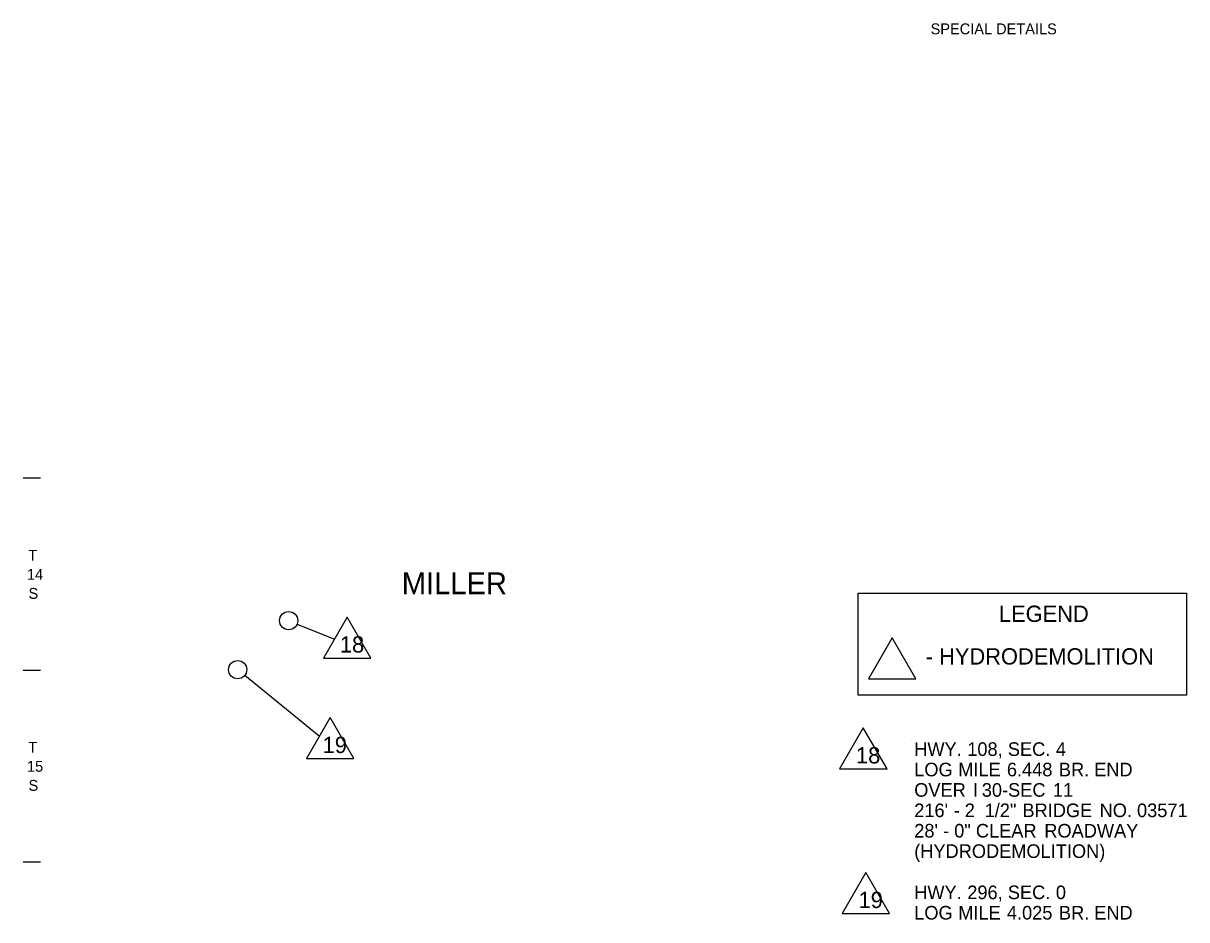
# Model space of a CAD drawing. Extents: x -17668 to 16999, y -17303 to 5867.
# Drawn here: x 10585 to 16998, y -12386 to -7443 of the extents above; entities that cross this region are included whole.
import ezdxf

# ---------------------------------------------------------------- set-up
doc = ezdxf.new("R2010")
doc.units = 0
for name, color, linetype in [('2', 7, 'Continuous'), ('42', 7, 'Continuous'), ('48', 7, 'Continuous'), ('Default', 7, 'Continuous')]:
    doc.layers.add(name, color=color, linetype=linetype)

msp = doc.modelspace()

# ---------------------------------------------------------------- linework, layer by layer
at = {"layer": '48'}
for p, q in [((12094.1, -10756), (12300.3, -10839.1)), ((12370.9, -10716.9), (12240.3, -10943.1)), ((12501.5, -10943.1), (12370.9, -10716.9)), ((15374.6, -10830.8), (15244, -11057)), ((15505.2, -11057), (15374.6, -10830.8)), ((12240.3, -10943.1), (12501.5, -10943.1)), ((12216.9, -11373.6), (11805.8, -11038.5)), ((15244, -11057), (15505.2, -11057)), ((12276.1, -11271.1), (12145.5, -11497.3)), ((12406.7, -11497.3), (12276.1, -11271.1)), ((15215.3, -11328.3), (15084.7, -11554.5)), ((15345.9, -11554.5), (15215.3, -11328.3)), ((15481.4, -11392.6), (15481.4, -11392.6)), ((12145.5, -11497.3), (12406.7, -11497.3)), ((15084.7, -11554.5), (15345.9, -11554.5)), ((15229.9, -12125.8), (15099.3, -12352)), ((15360.5, -12352), (15229.9, -12125.8)), ((15099.3, -12352), (15360.5, -12352))]:
    msp.add_line(p, q, dxfattribs=at)
msp.add_lwpolyline([(15186.8, -10584.9), (16997.4, -10584.9), (16997.4, -11147.5), (15186.8, -11147.5)], close=True, dxfattribs=at)
for centre in [(12048, -10736.7), (11767, -11006.9)]:
    msp.add_circle(centre, 50, dxfattribs=at)
at = {"layer": 'Default'}
for p, q in [((10680.3, -9951.1), (10585.3, -9951.1)), ((10680.3, -11011.5), (10585.3, -11011.5)), ((10680.3, -12068.3), (10585.3, -12068.3))]:
    msp.add_line(p, q, dxfattribs=at)

# ---------------------------------------------------------------- texts
at = {"layer": '2'}
for s, p in [('T', (10613.2, -10406.3)), ('14', (10605.9, -10511.3)), ('S', (10614.4, -10616.3)), ('T', (10613.2, -11464.9)), ('15', (10605.9, -11569.9)), ('S', (10614.4, -11674.9))]:
    msp.add_text(s, height=60, rotation=360, dxfattribs=at).set_placement(p)
msp.add_text('MILLER', height=120, dxfattribs=at).set_placement((12671.5, -10590.7))
at = {"layer": '42'}
msp.add_text('SPECIAL DETAILS', height=60, dxfattribs=at).set_placement((15586.1, -7503.5))
at = {"layer": '48'}
for s, p in [('LEGEND', (15963, -10743.8)), ('18', (12330.5, -10912.7)), ('- HYDRODEMOLITION', (15559.6, -10978.7)), ('19', (12235.3, -11466.9)), ('18', (15174.9, -11524.1)), ('19', (15189.2, -12321.6))]:
    msp.add_text(s, height=90, dxfattribs=at).set_placement(p)
at = {"layer": 'Default'}
for s, p in [('HWY.', (15496, -11482.6)), (' 108,', (15760.5, -11482.6)), (' SEC.', (15984.1, -11482.6)), (' 4', (16248.7, -11482.6)), ('LOG', (15496, -11595.1)), (' MILE', (15710.7, -11595.1)), (' 6.448', (15978.8, -11595.1)), (' BR.', (16265.4, -11595.1)), (' END', (16460, -11595.1)), ('OVER', (15496, -11707.6)), (' I', (15791.6, -11707.6)), (' 30-SEC', (15840.5, -11707.6)), (' 11', (16232.3, -11707.6)), ("216'", (15496, -11820.1)), (' -', (15685.9, -11820.1)), (' 2', (15746.6, -11820.1)), ('  1/2"', (15828.4, -11820.1)), (' BRIDGE', (16064.5, -11820.1)), (' NO.', (16489.8, -11820.1)), (' 03571', (16696, -11820.1)), ("28'", (15496, -11932.6)), (' 0"', (15688.3, -11932.6)), (' CLEAR', (15808, -11932.6)), (' ROADWAY', (16185.1, -11932.6)), (' -', (15627.6, -11932.6)), ('(HYDRODEMOLITION)', (15496, -12045.1)), ('HWY.', (15496, -12272.3)), (' 296,', (15760.5, -12272.3)), (' SEC.', (15984.1, -12272.3)), (' 0', (16248.7, -12272.3)), ('LOG', (15496, -12384.8)), (' MILE', (15710.7, -12384.8)), (' 4.025', (15978.8, -12384.8)), (' BR.', (16265.8, -12384.8)), (' END', (16460.5, -12384.8))]:
    msp.add_text(s, height=75, dxfattribs=at).set_placement(p)

doc.saveas('drawing.dxf')
